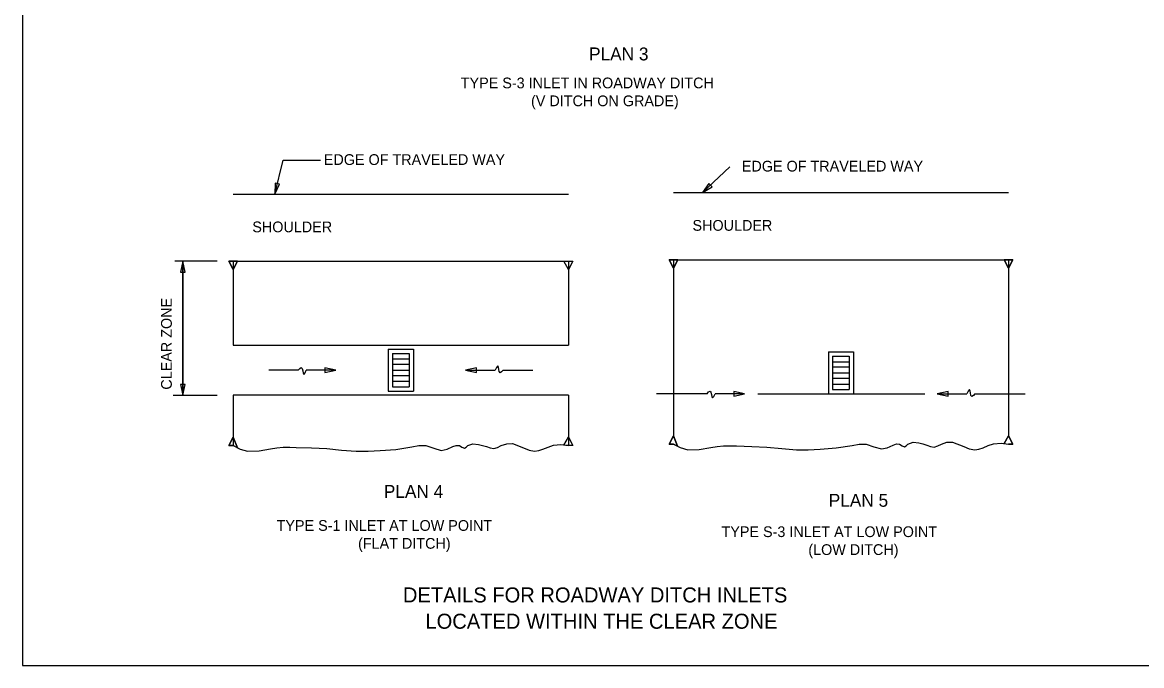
# Model space of a CAD drawing. Extents: x -439.1 to -407.9, y -458.1 to -437.7.
# Drawn here: x -439.11 to -423.48, y -458.05 to -449.07 of the extents above; entities that cross this region are included whole.
import ezdxf

# ---------------------------------------------------------------- set-up
doc = ezdxf.new("R2010")
doc.units = 0
for name, color, linetype in [('Bridge-Named Boundary', 7, 'Continuous'), ('Common-Notes', 7, 'Continuous'), ('Level 4', 7, 'Continuous')]:
    doc.layers.add(name, color=color, linetype=linetype)

msp = doc.modelspace()

# ---------------------------------------------------------------- linework, layer by layer
at = {"layer": 'Bridge-Named Boundary'}
msp.add_lwpolyline([(-439.109, -458.051), (-407.859, -458.051), (-407.859, -437.676), (-439.109, -437.676)], close=True, dxfattribs=at)
at = {"layer": 'Level 4'}
for p, q in [((-435.586, -451.468), (-435.468, -450.991)), ((-435.468, -450.991), (-434.947, -450.991)), ((-429.613, -451.447), (-429.231, -451.085)), ((-436.166, -451.468), (-431.487, -451.468)), ((-430.021, -451.447), (-425.342, -451.447)), ((-436.392, -452.404), (-436.979, -452.404)), ((-436.869, -454.276), (-436.869, -452.404)), ((-436.869, -452.404), (-436.869, -454.276)), ((-436.166, -452.521), (-436.228, -452.404)), ((-436.228, -452.404), (-436.166, -452.404)), ((-436.166, -452.404), (-431.487, -452.404)), ((-436.106, -452.404), (-436.166, -452.521)), ((-436.166, -452.404), (-436.166, -453.575)), ((-431.487, -452.521), (-431.549, -452.404)), ((-431.487, -452.404), (-431.426, -452.404)), ((-431.426, -452.404), (-431.487, -452.521)), ((-431.487, -452.404), (-431.487, -453.575)), ((-430.021, -452.501), (-430.081, -452.384)), ((-430.081, -452.384), (-430.021, -452.384)), ((-430.021, -452.384), (-425.342, -452.384)), ((-429.96, -452.384), (-430.021, -452.501)), ((-430.021, -452.384), (-430.021, -454.841)), ((-425.342, -452.501), (-425.402, -452.384)), ((-425.342, -452.384), (-425.281, -452.384)), ((-425.281, -452.384), (-425.342, -452.501)), ((-425.342, -452.384), (-425.342, -454.841)), ((-436.166, -453.575), (-431.487, -453.575)), ((-434.003, -453.632), (-433.651, -453.632)), ((-434.003, -453.632), (-434.003, -454.218)), ((-433.944, -453.691), (-433.71, -453.691)), ((-433.944, -453.691), (-433.944, -454.159)), ((-433.71, -453.691), (-433.71, -454.159)), ((-433.651, -453.632), (-433.651, -454.218)), ((-427.857, -453.671), (-427.857, -454.255)), ((-427.857, -453.671), (-427.506, -453.671)), ((-427.799, -453.728), (-427.565, -453.728)), ((-427.799, -453.728), (-427.799, -454.197)), ((-427.565, -453.728), (-427.565, -454.197)), ((-427.506, -453.671), (-427.506, -454.255)), ((-433.944, -453.768), (-433.71, -453.768)), ((-433.71, -453.847), (-433.944, -453.847)), ((-427.799, -453.807), (-427.565, -453.807)), ((-427.565, -453.885), (-427.799, -453.885)), ((-435.257, -453.925), (-435.67, -453.925)), ((-434.733, -453.925), (-435.145, -453.925)), ((-433.944, -453.925), (-433.71, -453.925)), ((-433.71, -454.004), (-433.944, -454.004)), ((-432.921, -453.925), (-432.509, -453.925)), ((-432.397, -453.925), (-431.985, -453.925)), ((-427.799, -453.962), (-427.565, -453.962)), ((-427.565, -454.041), (-427.799, -454.041)), ((-434.003, -454.218), (-433.651, -454.218)), ((-433.944, -454.081), (-433.71, -454.081)), ((-433.944, -454.159), (-433.71, -454.159)), ((-427.799, -454.119), (-427.565, -454.119)), ((-427.799, -454.197), (-427.565, -454.197)), ((-437.002, -454.276), (-436.392, -454.276)), ((-436.166, -454.276), (-436.166, -454.978)), ((-431.487, -454.276), (-436.166, -454.276)), ((-431.487, -454.276), (-431.487, -454.978)), ((-429.551, -454.255), (-430.255, -454.255)), ((-429.027, -454.255), (-429.438, -454.255)), ((-428.842, -454.255), (-426.51, -454.255)), ((-427.857, -454.255), (-427.506, -454.255)), ((-426.336, -454.255), (-425.924, -454.255)), ((-425.812, -454.255), (-425.108, -454.255)), ((-430.021, -454.841), (-430.081, -454.958)), ((-429.962, -454.987), (-430.021, -454.841)), ((-425.403, -454.95), (-425.342, -454.841)), ((-425.342, -454.841), (-425.281, -454.958)), ((-436.166, -454.862), (-436.228, -454.978)), ((-436.228, -454.978), (-436.166, -454.978)), ((-436.107, -455.008), (-436.166, -454.862)), ((-431.548, -454.971), (-431.487, -454.862)), ((-431.487, -454.862), (-431.426, -454.978)), ((-431.426, -454.978), (-431.487, -454.978)), ((-430.081, -454.958), (-430.02, -454.958)), ((-425.281, -454.958), (-425.342, -454.958))]:
    msp.add_line(p, q, dxfattribs=at)
for points in [[(-435.58, -451.313), (-435.586, -451.468), (-435.519, -451.328)], [(-429.524, -451.32), (-429.613, -451.447), (-429.481, -451.366)], [(-436.837, -452.556), (-436.869, -452.404), (-436.9, -452.556)], [(-436.228, -452.404), (-436.166, -452.521), (-436.106, -452.404)], [(-431.426, -452.404), (-431.487, -452.521), (-431.549, -452.404)], [(-430.081, -452.384), (-430.021, -452.501), (-429.96, -452.384)], [(-425.402, -452.384), (-425.342, -452.501), (-425.281, -452.384)], [(-434.885, -453.957), (-434.733, -453.925), (-434.885, -453.893)], [(-432.769, -453.893), (-432.921, -453.925), (-432.769, -453.957)], [(-436.9, -454.124), (-436.869, -454.276), (-436.837, -454.124)], [(-429.179, -454.287), (-429.027, -454.255), (-429.179, -454.224)], [(-426.184, -454.224), (-426.336, -454.255), (-426.184, -454.287)], [(-430.081, -454.958), (-430.021, -454.841), (-429.962, -454.987), (-430.02, -454.958)], [(-425.281, -454.958), (-425.342, -454.841), (-425.403, -454.95), (-425.342, -454.957)], [(-436.228, -454.978), (-436.166, -454.862), (-436.107, -455.008), (-436.167, -454.978)], [(-431.548, -454.971), (-431.487, -454.862), (-431.426, -454.978), (-431.487, -454.978)]]:
    msp.add_lwpolyline(points, close=True, dxfattribs=at)
for points in [[(-435.257, -453.925), (-435.236, -453.9), (-435.215, -453.887), (-435.203, -453.904), (-435.196, -453.936), (-435.19, -453.969), (-435.182, -453.984), (-435.163, -453.963), (-435.145, -453.925)], [(-432.397, -453.925), (-432.418, -453.95), (-432.439, -453.963), (-432.451, -453.946), (-432.458, -453.914), (-432.464, -453.882), (-432.472, -453.866), (-432.491, -453.887), (-432.509, -453.925)], [(-429.551, -454.255), (-429.53, -454.23), (-429.508, -454.218), (-429.496, -454.234), (-429.489, -454.267), (-429.484, -454.299), (-429.475, -454.314), (-429.456, -454.294), (-429.438, -454.255)], [(-425.812, -454.255), (-425.833, -454.281), (-425.854, -454.293), (-425.867, -454.277), (-425.874, -454.244), (-425.879, -454.212), (-425.888, -454.196), (-425.907, -454.217), (-425.924, -454.255)], [(-436.167, -454.978), (-436.069, -455.028), (-435.965, -455.057), (-435.805, -455.054), (-435.643, -455.024), (-435.555, -455.01), (-435.467, -455.002), (-435.376, -455.001), (-435.285, -455.004), (-435.072, -455.009), (-434.859, -455.021), (-434.655, -455.042), (-434.45, -455.058), (-434.283, -455.057), (-434.115, -455.048), (-433.894, -455.031), (-433.673, -454.998), (-433.574, -454.978), (-433.476, -454.978), (-433.367, -455.016), (-433.261, -455.045), (-433.181, -455.029), (-433.099, -454.993), (-433.053, -454.976), (-433.008, -454.978), (-432.972, -455.001), (-432.938, -455.014), (-432.915, -455), (-432.891, -454.978), (-432.819, -454.953), (-432.741, -454.963), (-432.684, -454.976), (-432.629, -454.993), (-432.578, -455.012), (-432.527, -455.021), (-432.475, -455.005), (-432.423, -454.978), (-432.346, -454.953), (-432.268, -454.951), (-432.112, -455.01), (-432.036, -455.043), (-431.958, -455.057), (-431.901, -455.048), (-431.844, -455.03), (-431.77, -454.999), (-431.695, -454.975), (-431.592, -454.965), (-431.487, -454.978)], [(-430.02, -454.958), (-429.924, -455.007), (-429.82, -455.036), (-429.659, -455.033), (-429.497, -455.003), (-429.409, -454.989), (-429.321, -454.982), (-429.23, -454.981), (-429.139, -454.983), (-428.926, -454.989), (-428.714, -455), (-428.509, -455.021), (-428.304, -455.038), (-428.137, -455.037), (-427.97, -455.027), (-427.749, -455.01), (-427.527, -454.977), (-427.428, -454.958), (-427.33, -454.957), (-427.222, -454.995), (-427.115, -455.024), (-427.035, -455.008), (-426.953, -454.973), (-426.907, -454.955), (-426.863, -454.957), (-426.826, -454.981), (-426.792, -454.994), (-426.769, -454.98), (-426.746, -454.957), (-426.674, -454.933), (-426.595, -454.942), (-426.538, -454.955), (-426.483, -454.973), (-426.432, -454.992), (-426.382, -455), (-426.33, -454.984), (-426.278, -454.957), (-426.201, -454.932), (-426.123, -454.93), (-425.967, -454.989), (-425.89, -455.022), (-425.812, -455.036), (-425.755, -455.028), (-425.698, -455.009), (-425.624, -454.979), (-425.55, -454.954), (-425.446, -454.945), (-425.342, -454.957)]]:
    msp.add_lwpolyline(points, dxfattribs=at)

# ---------------------------------------------------------------- texts
at = {"layer": 'Common-Notes'}
for s, height, p in [('PLAN 3', 0.18, (-431.198, -449.6)), ('PLAN 4', 0.18, (-434.063, -455.709)), ('PLAN 5', 0.18, (-427.852, -455.833)), ('DETAILS FOR ROADWAY DITCH INLETS', 0.21, (-433.797, -457.169)), ('LOCATED WITHIN THE CLEAR ZONE', 0.21, (-433.482, -457.536))]:
    msp.add_text(s, height=height, dxfattribs=at).set_placement(p)
at = {"layer": 'Level 4'}
for s, p in [('TYPE S-3 INLET IN ROADWAY DITCH', (-432.989, -449.99)), ('(V DITCH ON GRADE)', (-432.008, -450.24)), ('EDGE OF TRAVELED WAY', (-434.901, -451.06)), ('EDGE OF TRAVELED WAY', (-429.065, -451.152)), ('SHOULDER', (-435.899, -452)), ('SHOULDER', (-429.754, -451.979)), ('TYPE S-1 INLET AT LOW POINT', (-435.56, -456.169)), ('TYPE S-3 INLET AT LOW POINT', (-429.349, -456.256)), ('(FLAT DITCH)', (-434.423, -456.419)), ('(LOW DITCH)', (-428.137, -456.506))]:
    msp.add_text(s, height=0.15, dxfattribs=at).set_placement(p)
msp.add_text('CLEAR ZONE', height=0.15, rotation=90, dxfattribs=at).set_placement((-437.023, -454.198))

doc.saveas('drawing.dxf')
